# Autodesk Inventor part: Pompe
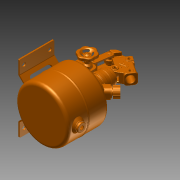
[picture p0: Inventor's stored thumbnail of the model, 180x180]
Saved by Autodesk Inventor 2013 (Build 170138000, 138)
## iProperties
Created: 2015-07
Part Number: Pompe
Material: Générique
Document SubType Name: Modeling
Designer: OL
Density: 1 g/cm^3
Norme de conversion: STEP AP203
Nom du fichier: P16S1+RP2.STEP
Préprocesseur: SolidWorks 2007
Postprocesseur: Build: 138, Release: 2013 RTM - Date: Thu 03/01/2012
Unités envoyées: millimètre
Incertitude: 1e-05
Author: OL
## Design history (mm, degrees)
node "P16S1+RP21"
feature "Composite1"
body "Srf1"
